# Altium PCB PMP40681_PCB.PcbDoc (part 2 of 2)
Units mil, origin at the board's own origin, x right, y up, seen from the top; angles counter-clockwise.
Board outline 1574.8 x 1574.8 mil, 4 copper layers (Top Layer, Signal Layer 1, Signal Layer 2, Bottom Layer), stack 67.2 mil thick; 42 components, 23 nets, 157 pads, 377 vias.
Unrouted connection lines stored in the file: 17.
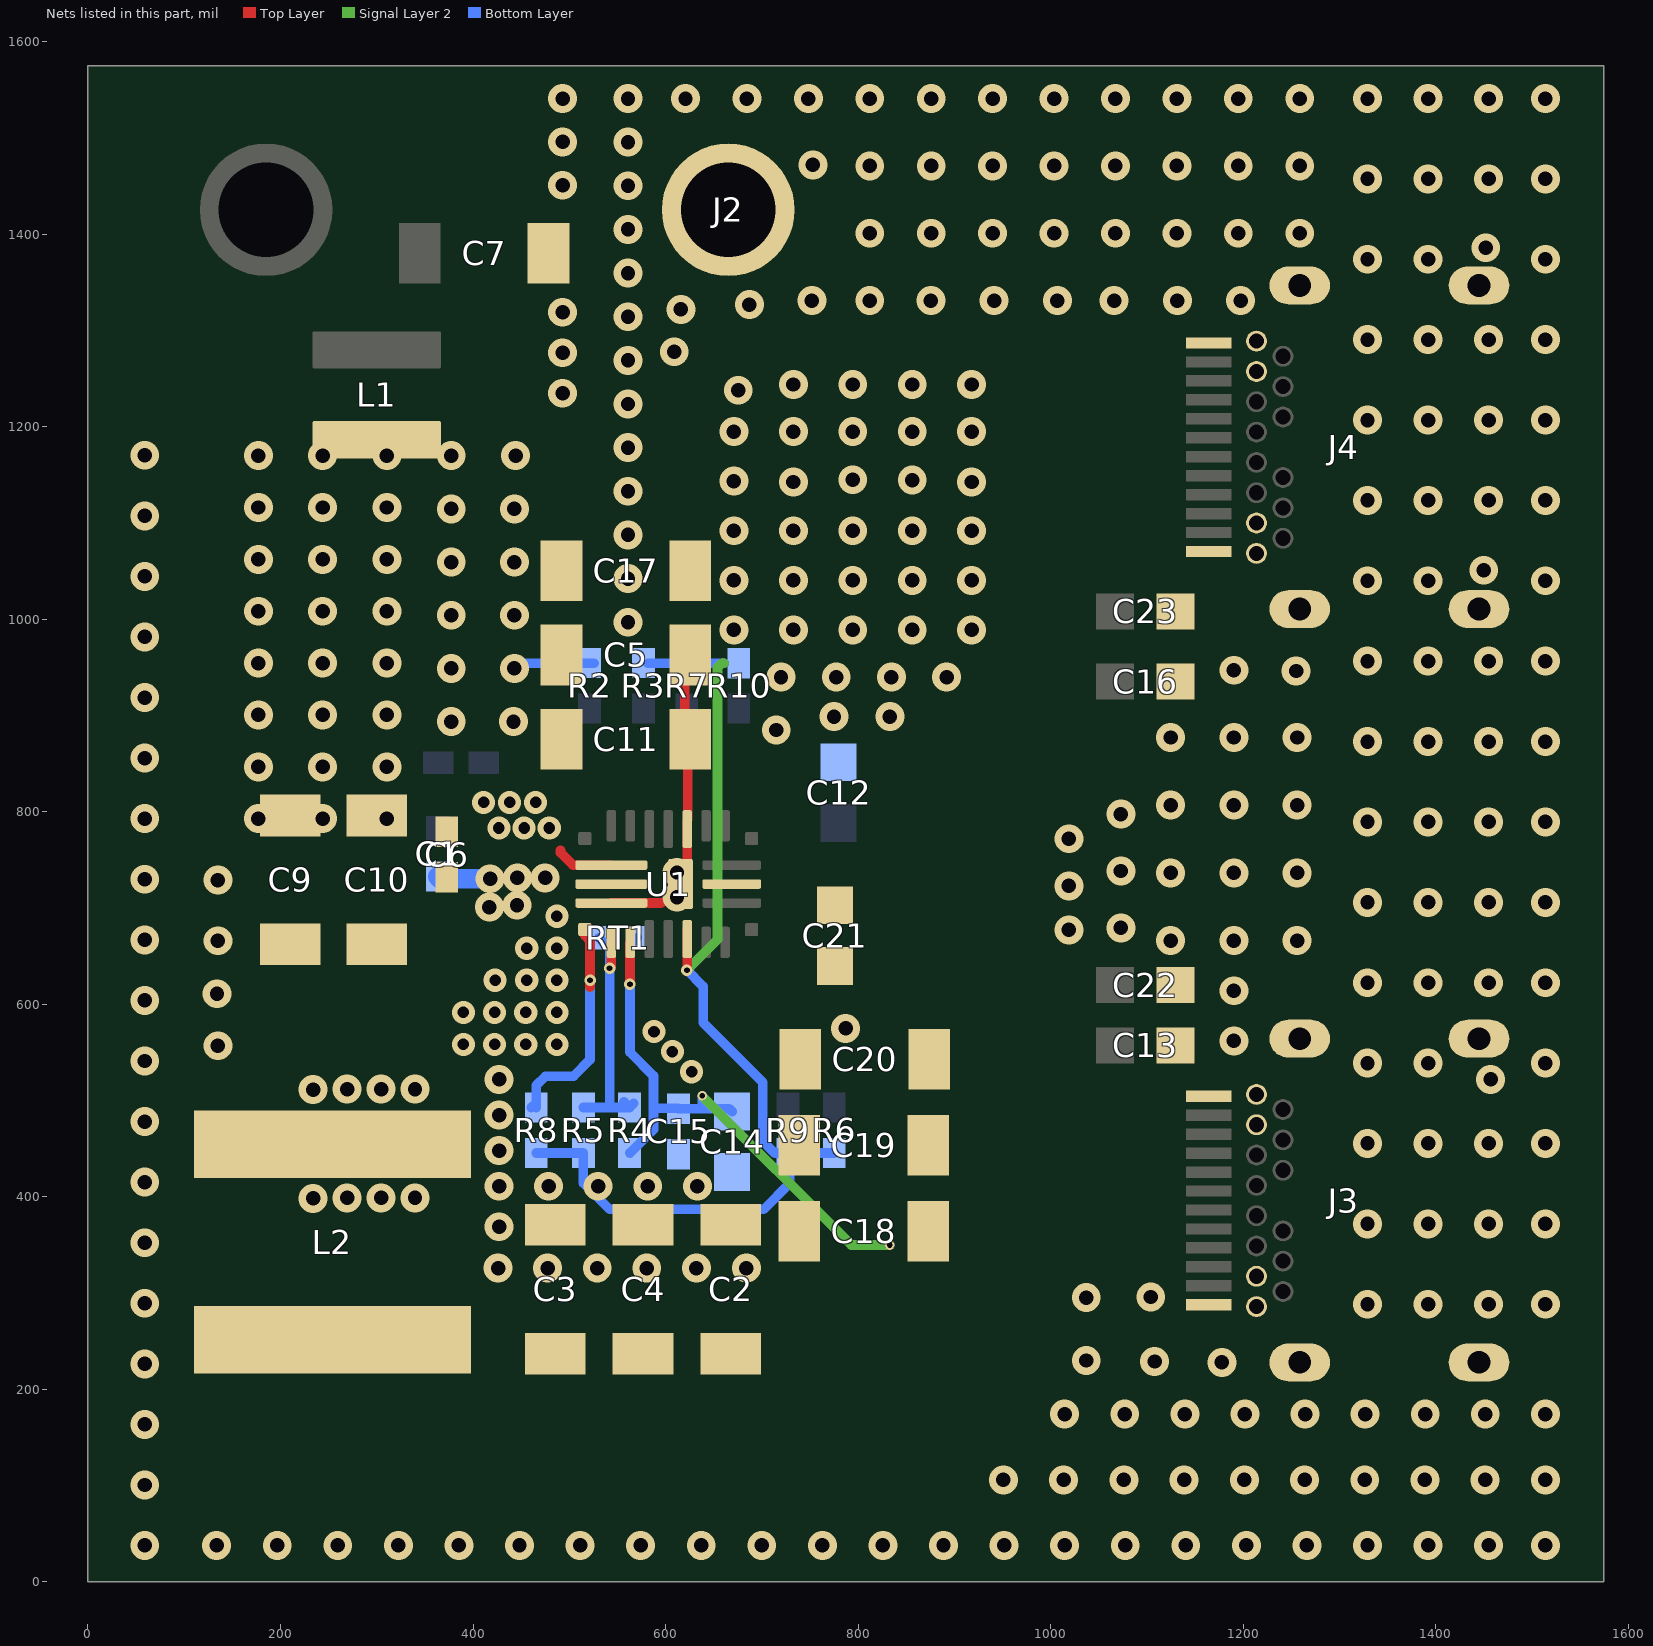
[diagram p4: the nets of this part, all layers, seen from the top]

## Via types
v1: diameter 30, hole 15, Top Layer to Bottom Layer, 321 vias
v2: diameter 24, hole 12, Top Layer to Bottom Layer, 28 vias
v3: diameter 12, hole 6, Top Layer to Bottom Layer, tented both sides, 14 vias
v4: diameter 12, hole 6, Top Layer to Bottom Layer, tented bottom, 6 vias
v5: diameter 10, hole 6, Top Layer to Bottom Layer, tented both sides, 5 vias
v6: diameter 24, hole 12, Top Layer to Bottom Layer, tented both sides, 3 vias

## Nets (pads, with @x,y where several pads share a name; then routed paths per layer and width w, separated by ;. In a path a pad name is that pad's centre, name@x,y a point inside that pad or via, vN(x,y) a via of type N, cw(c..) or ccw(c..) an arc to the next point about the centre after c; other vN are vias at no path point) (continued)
PGND: C2.2 C3.2 C4.2 C5.2 C6.2 C7.2 C9.2 C10.2 C11.2 C12.2 C13.2 C14.2 C15.2 C16.2 C17.2 C18.2 C19.2 C20.2 C21.2 C22.2 C23.2 J2.1 J3.A1 J3.A12 J3.B1 J3.B12 J3.M1 J3.M2 J3.S1 J3.S2 J3.S3 J3.S4 J4.A1 J4.A12 J4.B1 J4.B12 J4.M1 J4.M2 J4.S1 J4.S2 J4.S3 J4.S4 R3.1 R5.1 R6.2 R7.1 R8.2 R9.1 R10.1 U1.6 U1.16 U1.24 U1.25 | length 1417.7
  Top Layer w10: U1.24@543.71,705.27 595.34,705.27 595.56,705.48 ; C5.2@610.51,962.43 619.85,953.09 619.85,894.63 612.08,886.86 C11.2@622.18,877.76 ; U1.25@615.56,724.95 622.45,731.84 U1.16@622.45,782.04 622.45,791.45 623,792 623,876.84 622.13,877.71 C11.2@622.18,877.76 ; C11.2@621.18,878.96 C11.2@622.18,877.76 ; v3@622.45,639.92 U1.6@622.45,667.86 U1.6@622.45,678.64
  Signal Layer 2 w10: v3(622.13,635.48) 654,667.35 654,950 658.5,954.5 661,954.5
  Bottom Layer w10: R8.2@465.64,445.62 R5.1@514.64,445.62 514.64,414.36 542,387 702,387 728.85,413.85 R9.1@728.85,441.49 ; R3.1@581.5,954.5 629.85,954.5 661,954.5 ; v3(622.13,635.48) 639,618.61 639,581 700.81,519.19 700.81,458.19 713.38,445.62 750,445.62 ; R9.1@727.15,445.62 750,445.62 ; R6.2@775.2,445.62 750,445.62
  other v1: 59,38 133.63,38 196.56,38 259.48,38 322.41,38 385.33,38 448.26,38 511.19,38 574.11,38 637.04,38 699.96,38 762.89,38 825.82,38 888.74,38 951.67,38 1014.59,38 1077.52,38 1140.44,38 1203.37,38 1266.3,38 1329.22,38 1392.15,38 1455.07,38 1514,38 59,100.71 951,106 1013.56,106 1076.11,106 1138.67,106 1201.22,106 1263.78,106 1326.33,106 1388.89,106 1451.44,106 1514,106 59,163.63 1014.59,174.33 1077.02,174.33 1139.44,174.33 1201.87,174.33 1264.3,174.33 1326.72,174.33 1389.15,174.33 1451.57,174.33 1514,174.33 59,226.56 1178,228 1108,229 1037,230 1329.22,288.5 1392.15,288.5 1455.07,288.5 1514,288.5 59,289.48 1037,295.33 1104,296 426,326 477.5,326 529,326 580.5,326 632,326 684,326 59,352.41 427,369 1329.22,372 1392.15,372 1455.07,372 1514,372 427,411 478.5,411 530,411 581.5,411 633,411 59,415.33 427,448 1329.22,455.5 1392.15,455.5 1455.07,455.5 1514,455.5 59,478.26 427,485 427,522 1457,522 1329.22,539 1392.15,539 1514,539 59,541.19 135,557 1190.33,562 787,575 59,604.11 134,611 1190.33,614.12 1329.22,622.5 1392.15,622.5 1455.07,622.5 1514,622.5 135,666.07 1124.67,666.24 1190.33,666.24 1256,666.24 59,667.04 1019,677.37 1073,679.43 1329.22,706 1392.15,706 1455.07,706 1514,706 611.85,711.48 1019,723.02 135,729 59,729.96 611.85,736.97 1124.67,736.58 1190.33,736.58 1256,736.58 1073,738.52 1019,772 1329.22,789.5 1392.15,789.5 1455.07,789.5 1514,789.5 59,792.89 1073,797.61 1124.67,806.91 1190.33,806.91 1256,806.91 59,855.82 1329.22,873 1392.15,873 1455.07,873 1514,873 1124.67,877.24 1190.33,877.24 1256,877.24 715,885 775,899 833,899 59,918.74 719.92,940 777.28,940 834.64,940 892,940 1255,946.28 1190.33,947.11 1329.22,956.5 1392.15,956.5 1455.07,956.5 1514,956.5 59,981.67 671,989 732.75,989 794.5,989 856.25,989 918,989 561,997 671,1040.5 732.75,1040.5 794.5,1040.5 856.25,1040.5 918,1040.5 1329.22,1040 1392.15,1040 1514,1040 561,1042.33 59,1044.59 1450,1051 561,1087.67 671,1092 732.75,1092 794.5,1092 856.25,1092 918,1092 59,1107.52 1329.22,1123.5 1392.15,1123.5 1455.07,1123.5 1514,1123.5 561,1133 671,1143.5 732.75,1142.67 918,1142.67 794.5,1145 856.25,1144.6 59,1170.44 561,1178.33 671,1195 732.75,1195 794.5,1195 856.25,1195 918,1195 1329.22,1207 1392.15,1207 1455.07,1207 1514,1207 561,1223.67 493.11,1234.9 675.46,1237.91 732.75,1243.91 794.5,1243.91 856.25,1243.91 918,1243.91 561,1269 493.11,1276.95 609,1278 1329.22,1290.5 1392.15,1290.5 1455.07,1290.5 1514,1290.5 561,1314.33 493.11,1319 616,1322 687,1327 752,1331 812.14,1331 875.67,1331 941.33,1331 1007,1331 1066,1331 1131.67,1331 1197.33,1331 561,1359.67 1329.22,1374 1392.15,1374 1514,1374 1452,1386 812.14,1401 875.94,1401 939.75,1401 1003.55,1401 1067.36,1401 1131.16,1401 1194.97,1401 1258.78,1401 561,1405 561,1450.33 493.11,1450.95 1329.22,1457.5 1392.15,1457.5 1455.07,1457.5 1514,1457.5 812.14,1471 875.94,1471 939.75,1471 1003.55,1471 1067.36,1471 1131.16,1471 1194.97,1471 1258.78,1471 753,1472 493.11,1495.97 561,1495.67 493.11,1541 561,1541 620.72,1541 684.52,1541 748.33,1541 812.14,1541 875.94,1541 939.75,1541 1003.55,1541 1067.36,1541 1131.16,1541 1194.97,1541 1258.78,1541 1329.22,1541 1392.15,1541 1455.07,1541 1514,1541
  other v2: 390,558.46 422.39,558.46 454.79,558.46 487.18,558.46 390,591.73 422.39,591.73 454.79,591.73 487.18,591.73 423,625 455.78,625 487.18,625 455.78,658.28 487.18,658.28 487.18,691.55
  other v6: 627,530 607,551 588,571.64
SENS: C2.1 C3.1 C4.1 C14.1 C15.1 C18.1 C19.1 C20.1 C21.1 L2.2 R4.2 RT1.2 U1.3 U1.11 | length 647.6
  Top Layer w10: v3(563,621) 563,664.03 U1.3@563.39,664.42
  Signal Layer 2 w10: v5(638,505) 793,350 v5(832.79,350)
  Bottom Layer w10: R4.2@562.64,445.62 563.07,445.62 587.45,470 587.45,492 ; RT1.2@570.56,669.24 563,661.68 v3(563,621) 563,550.25 587.45,525.81 587.45,492 ; v5(638,505) 638,494.62 637,493.62 639,491.62 ; C14.1@669.11,488.76 666.24,491.62 639,491.62 ; 587.45,492 613.03,492 C15.1@613.41,491.62 639,491.62
SW: C1.1 L2.1 U1.23 | length 59
  Bottom Layer w10: v1@415.5,732.76 v1(417.79,730.46)
  Bottom Layer w20: C1.1@363,732.76 365.29,730.46 v1(417.79,730.46)
  other v1: 233.84,398.35 269.13,398.98 304.42,398.98 339.71,398.98 233.84,511.39 269.13,512.02 304.42,512.02 339.71,512.02 417,701 445.64,703 446,731.38 474.85,731.38
TS: R4.1 R5.2 RT1.1 U1.2 | length 271.7
  Top Layer w10: v3(541.85,637.48) 543.71,639.34 U1.2@543.71,664.42
  Bottom Layer w10: R5.2@514.64,492.86 540,492.86 ; RT1.1@530.56,669.24 541.85,657.95 v3(541.85,637.48) 541.85,494.71 540,492.86 ; R4.1@556.85,498.65 R4.1@562.64,492.86 ; R4.1@566.85,497.08 R4.1@562.64,492.86 ; 540,492.86 R4.1@562.64,492.86
VIN: C5.1 C6.1 C9.1 C10.1 C11.1 C17.1 L1.2 R2.2 U1.22 | length 145.8
  Top Layer w10: 490.85,759.98 490.85,757.62 503.84,744.64 U1.22@543.71,744.64
  Bottom Layer w10: v1(443,948.98) 448.52,954.5 R2.2@525.96,954.5
  other v1: 177,792.89 243.79,792.89 310.58,792.89 177,846.76 243.79,846.76 310.58,846.76 377.36,893.72 442,893.72 177,900.64 243.79,900.64 310.58,900.64 377.36,948.98 177,954.51 243.79,954.51 310.58,954.51 377.36,1004.23 443,1004.23 177,1008.38 243.79,1008.38 310.58,1008.38 377.36,1059.49 443,1059.49 177,1062.25 243.79,1062.25 310.58,1062.25 377.36,1114.74 443,1114.74 177,1116.13 243.79,1116.13 310.58,1116.13 177,1170 243.79,1170 310.58,1170 377.36,1170 444.15,1170
  other v2: 426.85,783.19 452.99,783.19 479.14,783.19 411,809.75 438,809.75 465,809.75
VSET: R8.1 U1.1 | length 238.1
  Top Layer w10: U1.1@516.15,677.71 516.15,671.41 521.56,666 v3(521.56,625) 521.56,617.79
  Bottom Layer w10: R8.1@460.64,492.86 R8.1@463.14,495.36 ; R8.1@465.64,492.86 465.64,515.79 475.17,525.32 504.39,525.32 521.56,542.49 v3(521.56,625)
pads on no net: J3.A2 J3.A3 J3.A8 J3.A10 J3.A11 J3.B2 J3.B3 J3.B8 J3.B10 J3.B11 J4.A2 J4.A3 J4.A8 J4.A10 J4.A11 J4.B2 J4.B3 J4.B8 J4.B10 J4.B11
copper on no net: | length 10
  Top Layer w10: 1154.61,426.53 1155.39,425.75 1164.25,425.75

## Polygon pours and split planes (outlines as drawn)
PGND on Top Layer "TOP_LAYER_PGND_P106" (solid, remove dead copper, pour order 106): 1,1578.91 1575.8,1578.91 1575.8,4.11 1,4.11
SW on Top Layer "TOP_LAYER_SW_P104" (solid, remove dead copper, pour order 104): 380,380 401,401 401,504 375.03,529.97 127.97,529.97 107,509 107,402 129,380
INPUT on Top Layer "TOP_LAYER_INPUT_P097" (solid, remove dead copper, pour order 97): 400,1285 369.46,1254.46 26.54,1254.46 0,1281 0,1574.8 400,1574.8
PA_BUS on Top Layer "TOP_LAYER_PA_BUS_P064" (solid, remove dead copper, pour order 64): 998.76,353.24 999.25,637.25 1008,646 1087,646 1096,637 1096,504.02 1111.69,488.33 1148.74,451.28 1162.84,451.33 1162.84,441.49 1162.84,363.3 1162.84,331.59 1020.92,331.08
SW on Top Layer "TOP_LAYER_SW_P008" (solid, remove dead copper, pour order 8): 437.04,672.54 412.87,672.54 400.79,684.62 400.79,738.32 411.56,749.08 479.9,749.08 496.74,732.24 592.85,732.24 592.85,719.05 483.54,719.04
PB_BUS on Top Layer "TOP_LAYER_PB_BUS_P024" (solid, remove dead copper, pour order 24): 638.75,752 689.85,752 721.92,784.06 722.1,825.74 769.73,873.46 858.06,873.46 963,978.4 963,1198 1018.85,1253.85 1114.82,1253.85 1132.1,1236.56 1221.16,1236.56 1227.05,1230.67 1227.05,1115.75 1141.92,1115.75 1092,1065.83 1092,892.49 953.8,754.28 719.92,754.29 705.64,740.01 639.24,740.01 638.33,740.93 638.75,741.36
VIN on Top Layer "TOP_LAYER_VIN_P010" (solid, remove dead copper, pour order 10): 120.8,1179.21 153.86,1213.19 473.55,1213.19 520.32,1166.43 520.32,808.61 508.05,796.34 508.07,749.56 564.38,749.56 564.38,739.71 508.08,739.71 500.14,739.71 482.55,757.3 163.53,757.3 120.8,800.02
SENS on Top Layer "TOP_LAYER_SENS_P004" (solid, remove dead copper, pour order 4): 739.09,701.84 759.94,681 800.54,681 812,669.54 812,344.8 767.2,300 120,300 98,278 98,154.87 132.87,120 915,120 990,195 990,714.24 958.24,746 722.82,746 706.7,729.87 638.48,729.87 638.48,720.88 639.18,720.18 705,720.18 723.34,701.84
PA_BUS on Top Layer "TOP_LAYER_PA_BUS_P022" (solid, remove dead copper, pour order 22): 738.21,596.93 745.85,604.57 745.85,687.48 740.19,693.14 720.19,693.14 703.14,710.19 638.18,710.19 638.18,700.34 698.19,700.34 706.82,691.71 706.82,605.26 715.15,596.93
PGND on Bottom Layer "BOTTOM_LAYER_PGND_P089" (solid, remove dead copper, pour order 89): 0,1574.8 1574.8,1574.8 1574.8,0 0,0
SW on Bottom Layer "BOTTOM_LAYER_SW_P117" (solid, remove dead copper, pour order 117): 178,723.41 203.74,749.15 480.14,748.95 489.85,739.45 489.85,725.35 432.75,668.26 360,595.5 360,523.87 360,386.11 353.38,379.49 191.62,379.49 178,393.11
VIN on Bottom Layer "BOTTOM_LAYER_VIN_P110" (solid, remove dead copper, pour order 110): 383.5,816.09 397.91,830.5 428,830.5 474.5,830.5 497.11,807.89 497.11,770.08 484.13,757.1 479.86,757.1 383.5,757.23
PA_BUS on Signal Layer 2 "SIGNAL_LAYER_2_PA_BUS_P060" (solid, remove dead copper, pour order 60): 806.44,698 965,698 1087,576 1087,510 1063,486 986.71,486 980,492.71 880.98,598 714.63,598 704.51,608.12 704.51,688.92 713.59,698
PGND on Signal Layer 2 "SIGNAL_LAYER_2_PGND_P108" (solid, remove dead copper, pour order 108): 1,1571.8 1575.8,1571.8 1575.8,-3 1,-3
VIN on Signal Layer 2 "SIGNAL_LAYER_2_VIN_P091" (solid, remove dead copper, pour order 91): 499.84,740.01 482.75,757.1 480.14,757.1 163.72,757.1 120,800.82 120,1178.87 152.13,1211 462,1211 480.14,1192.86 480.14,855.71 568.61,767.24 568.49,748.75 559.76,740.01
SW on Signal Layer 2 "SIGNAL_LAYER_2_SW_P034" (solid, remove dead copper, pour order 34): 178,723.41 203.74,749.15 480.14,748.95 489.85,739.45 489.85,725.35 432.75,668.26 360,595.5 360,523.87 360,386.11 353.38,379.49 191.62,379.49 178,393.11
PGND on Signal Layer 1 "SIGNAL_LAYER_1_PGND_P107" (solid, remove dead copper, pour order 107): 0,1574.8 1574.8,1574.8 1574.8,0 0,0

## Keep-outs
Keep-Out Layer:
  text ".Layer_Name" at 577,-858.49 h60

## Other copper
Top Layer:
  pour cut-out: 99.46,398.88 102.1,396.24 102.1,293.64 102.98,293.64 116.88,307.54 408.46,307.54 410,309.08 404.08,315 404,315 404,391 387.23,374.23 123.23,374.23 101.23,396.23
  pour cut-out: 405,1564.61 448.59,1564.61 448.59,1245.99 405,1245.99
  pour cut-out: 447,1215 447,1254.46 5,1254.46 5,1215
  pour cut-out: 630,767.56 630,707.68 634.68,707.68 634.96,773.19
  pour cut-out: 586.55,714.81 590.08,718.34 590.08,747.65 586.26,751.48 584.85,751.48 584.31,751.73 583.03,750.45 583.03,714.81
  pour cut-out: 536.92,698.48 605.11,698.48 605.11,689.08 550.25,688.72 548.65,690.32 536.53,690.32
  text ".Layer_Name" at 577,-858.49 h60
Bottom Layer:
  pour cut-out: 522.8,688.99 523.05,689.24 587.07,689.24 587.07,684.28 587.03,684.24 522.8,684.24
  pour cut-out: 1258.31,428.23 1258.56,427.98 1258.56,363.96 1253.6,363.96 1253.56,364 1253.56,428.23
  pour cut-out: 1254.25,1145.77 1254,1146.02 1254,1210.04 1258.96,1210.04 1259,1210 1259,1145.77
  pour cut-out: 719.77,474.96 720.02,475.21 784.04,475.21 784.04,470.25 784,470.21 719.77,470.21
  pour cut-out: 459.22,471.87 546.06,472.21 546.06,469.03 459.22,468.98
  pour cut-out: 594.49,465.41 594.74,465.66 658.76,465.66 658.76,460.7 658.72,460.66 594.49,460.66
  pour cut-out: 545.77,930.75 546.02,931 610.04,931 610.04,926.04 610,926 545.77,926
  text ".Layer_Name" at 577,-858.49 h60

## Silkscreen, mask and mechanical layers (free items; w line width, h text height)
Top Overlay:
  text "VIN" at 341,1446 h72.83 r90
  text "GND" at 866.06,1411.15 h72.83 r90
  text "PMP40681E1" at 419,56 h50
  text ".Layer_Name" at 577,-858.49 h60
Bottom Overlay:
  text ".Layer_Name" at 577,-858.49 h60
Top Paste:
  text ".Layer_Name" at 577,-858.49 h60
Bottom Paste:
  text ".Layer_Name" at 577,-858.49 h60
Top Solder:
  region: 381.39,464.09 331.39,464.09 331.39,432.21 381.39,432.21
  region: 397,779 397,818 409.5,830.5 476.5,830.5 500.31,806.69 500.31,783.08 500.31,755.01 503.72,751.6 523.04,751.61 523.04,737.62 502.23,737.62 473.85,766 410,766
  region: 494,580 500.97,586.97 500.97,635.4 500.97,690.8 509.07,698.9 509.07,712.48 487.18,712.48 436,661.3 436,589 445,580
  region: 692.85,738.06 702.45,738.06 731.36,766.97 723.38,774.95 692.85,744.43
  region: 695.65,712.48 695.65,702.88 713.38,685.16 721.36,693.14 702.02,712.48
  region: 517.57,718.48 484.37,718.48 484.37,731.48 504.57,731.48 517.57,731.48
  region: 696.65,731.48 729.85,731.48 729.85,718.48 709.65,718.48 696.65,718.48
  text ".Layer_Name" at 577,-858.49 h60
  text ".Layer_Name" at 577,-858.49 h60
Bottom Solder:
  rectangle: 588,690 635,759
  text ".Layer_Name" at 577,-858.49 h60
Drill Guide:
  text ".Layer_Name" at 577,-858.49 h60
M1 Board Outline:
  lines w0.39: 0,1968.5 0,1968.5
  lines w1: 0,0 0,1574.8 1574.8,1574.8 1574.8,0 0,0
  text ".Layer_Name" at 577,-858.49 h60
M2 Board Dimensions:
  rectangle: 0,-275 125,-150
  rectangle: 125,-400 500,-275
  lines w7: 0,-275 1000,-275 ; 125,-400 125,-150 ; 250,-400 250,-150 ; 500,-400 500,-150 ; 750,-400 750,-150 ; 0,-400 1000,-400 1000,-150 0,-150 0,-400
  text ".Layer_Name" at 577,-858.49 h60
M3 3D STEP Top:
  text ".Layer_Name" at 577,-858.49 h60
M4 3D STEP Bottom:
  text ".Layer_Name" at 577,-858.49 h60
M5 Assembly Top:
  lines w10: -292,-930.17 6308,-930.17 ; -292,-726.83 6310,-726.83 ; -292,-523.5 -292,-1133.5 3713,-1133.5 6310,-1133.5 6310,-523.5 -291.5,-523.5 -291.5,-1133.5 1284,-1133.5 ; 2173,-1133.5 2173,-523.5 ; 3440,-726.83 3440,-523.5 ; 4280,-726.83 4280,-523.5 ; 4902,-1140 4902,-937.17
  text "COMPONENTS MARKED 'DNP' SHOULD NOT BE POPULATED." at 1153.5,-318.5 h60
  text "ASSEMBLY VARIANT:" at 1153,-434 h60
  text ".VariantName" at 2189,-434 h60
  text "PCB VIEWED FROM TOP SIDE" at -228.5,-655.67 h60
  text "BOARD #:" at 2248,-655.67 h60
  text ".PRJ_Number" at 2793.5,-655.67 h60
  text "REV:" at 3638,-655.67 h60
  text ".PCB_Rev" at 3929.5,-655.67 h60
  text "SVN REV:" at 4476,-655.67 h60
  text ".VersionControl_RevNumber" at 4982,-655.67 h60
  text "TID #:" at 2248,-859 h60
  text ".TID" at 2793.5,-859 h60
  text "PLOT NAME =" at -228.5,-1064.34 h60
  text ".plot_File_Name" at 577,-1064.34 h60
  text "GENERATED    :" at 2250,-1064.34 h60
  text ".Print_Date" at 3119.5,-1064.34 h60
  text ".Print_Time" at 3848.5,-1064.34 h60
  text "TEXAS INSTRUMENTS" at 5113,-1064.34 h60
M6 Assembly Bottom:
  lines w10: -292.5,-727.33 6309.5,-727.33 ; -290.5,-930.67 6309.5,-930.67 ; 1115.5,-1140.5 1115.5,-937.67 ; 1737.5,-727.33 1737.5,-524 ; 2577.5,-727.33 2577.5,-524 ; 3844.5,-1134 3844.5,-524 ; 4733.5,-1134 6309,-1134 6309,-524 -292.5,-524 -292.5,-1134 2304.5,-1134 6309.5,-1134 6309.5,-524
  text "COMPONENTS MARKED 'DNP' SHOULD NOT BE POPULATED." at 6102,-318 h60
  text ".VariantName" at 5058,-434 h60
  text "ASSEMBLY VARIANT:" at 6097,-434 h60
  text ".VersionControl_RevNumber" at 1035.5,-656.17 h60
  text "SVN REV:" at 1541.5,-656.17 h60
  text ".PCB_Rev" at 2088,-656.17 h60
  text "REV:" at 2379.5,-656.17 h60
  text ".PRJ_Number" at 3224,-656.17 h60
  text "BOARD #:" at 3769.5,-656.17 h60
  text "PCB VIEWED FROM BOTTOM SIDE" at 6246,-656.17 h60
  text ".TID" at 3224,-859.5 h60
  text "TID #:" at 3769.5,-859.5 h60
  text "TEXAS INSTRUMENTS" at 904.5,-1064.84 h60
  text ".Print_Time" at 2169,-1064.84 h60
  text ".Print_Date" at 2898,-1064.84 h60
  text "GENERATED    :" at 3767.5,-1064.84 h60
  text ".plot_File_Name" at 5440.5,-1064.84 h60
  text "PLOT NAME =" at 6246,-1064.84 h60
M9 Title Sheet:
  drawing of 57 lines, arcs and shapes, not listed
  text "1" at 739.84,8036.5 h70
  text "2" at 3235.5,8036.5 h70
  text "3" at 5724.84,8036.5 h70
  text "4" at 8231.51,8036.5 h70
  text "5" at 10730.5,8036.5 h70
  text "6" at 13235.5,8036.5 h70
  text "A" at -416.5,6893.5 h70
  text "A" at 14383.5,6893.5 h70
  text "B" at -416.5,4513.5 h70
  text "B" at 14383.5,4513.5 h70
  text "C" at -416.5,2138.5 h70
  text "C" at 14383.5,2138.5 h70
  text "PROJECT TITLE:" at 11343.5,277.5 h45
  text ".PRJ_Title" at 11393.5,144.17 h70
  text "DESIGNED FOR:" at 11343.5,-23.5 h45
  text ".PRJ_Customer" at 11393.5,-163.5 h70
  text "D" at -416.5,-231.5 h70
  text "D" at 14383.5,-231.5 h70
  text "FILE NAME:" at 11343.5,-323.5 h45
  text ".PCB_File_Name_No_Path" at 11393.5,-443.5 h70
  text "Texas Instruments (TI) and/or its licensors do not warrant the accuracy or completeness of this specification" at 6374,-605.34 h45
  text "ENGINEER:" at 11343.5,-613.5 h45
  text "LAYOUT BY:" at 12848.5,-613.5 h45
  text "or any information contained therein. TI and/or its licensors do not warrant that this design will meet" at 6329.01,-718 h45
  text ".PRJ_Engineer" at 11393.5,-768.49 h70
  text ".PCB_Layout" at 12899,-768.49 h70
  text "the specifications, will be suitable for your application or fit for any particular purpose, or will operate in" at 6329.01,-830.67 h45
  text ".Layer_Name" at 577,-858.49 h60
  text "ALTIUM DESIGNER VERSION:" at 12848.5,-923.5 h45
  text "an implementation. TI and/or its licensors do not warrant that the design is production worthy. You should" at 6329.01,-943.33 h45
  text "completely validate and test your design implementation to confirm the system functionality for your application." at 6374,-1056 h45
  text ".print_Scale" at 11393.5,-1056.83 h70
  text ".Application_BuildNumber" at 12899,-1056.83 h70
  text "1" at 739.84,-1263.5 h70
  text "2" at 3235.5,-1263.5 h70
  text "3" at 5724.84,-1263.5 h70
  text "4" at 8231.51,-1263.5 h70
  text "5" at 10730.5,-1263.5 h70
  text "6" at 13235.5,-1263.5 h70
M10 Fab Notes:
  drawing of 189 lines, arcs and shapes, not listed
  text "DESIGN INFORMATION" at 12382.02,6356.17 h60
  text "MIN. TRACK WIDTH:" at 11737.46,6224.05 h60
  text "8" at 12833.7,6224.05 h60
  text "MIL" at 12988.46,6224.05 h60
  text "MIN. CLEARANCE:" at 11737.46,6099.92 h60
  text "0.2" at 12773.7,6099.93 h60
  text "mm" at 12988.46,6099.92 h60
  text "MIN. VIA PAD SIZE:" at 11737.46,5975.8 h60
  text "24" at 12803.71,5975.8 h60
  text "MIL" at 12988.46,5975.8 h60
  text "0.05mm (2MIL)" at 12432.46,5845.9 h60
  text "MINIMUM ANNULAR RING" at 11408.23,5837.67 h60
  text "EXTERNAL" at 13140.46,5837.67 h60
  text "PER" at 11608.23,5727.55 h60
  text "IPC-D-275 CLASS 2 LEVEL C" at 11828.23,5727.54 h60
  text "MIL, HOLES" at 13316.46,5627.07 h60
  text "+/-" at 12924,5618.48 h60
  text "+/-" at 13778,5618.48 h60
  text "REGISTRATION TOLERANCES:" at 11408.23,5617.42 h60
  text "METAL" at 12608,5617.42 h60
  text "5" at 13184.2,5617.42 h60
  text "3" at 14017.2,5617.42 h60
  text "MIL" at 14133.46,5617.42 h60
  text "HOLE SIZE TOLERANCE (UNLESS OTHERWISE SPECIFIED):" at 11408.23,5519.1 h60
  text "+/-" at 13778,5516.23 h60
  text "3" at 14017.2,5515.17 h60
  text "MIL" at 14133.46,5515.17 h60
  text "MATERIAL:" at 11333.46,5377.52 h60
  text "FR-4 High Tg" at 12319.9,5249 h60
  text "X" at 12175.46,5241.01 h60
  text "FR-408" at 11754.46,5236.49 h60
  text "OTHER" at 13242.46,5236.49 h60
  text "62 MIL (1.6mm) +/-10%" at 12074.56,5093.46 h60
  text "X" at 11954.46,5091.01 h60
  text "THICKNESS:" at 11408.23,5085.24 h60
  text "OTHER" at 13359.46,5085.24 h60
  text "TOLERANCE:" at 11408.23,4946.92 h60
  text "X" at 12256.46,4946.92 h60
  text "ANSI IPC-6012 TYPE 3 CLASS 2" at 12434.48,4946.92 h60
  text "OTHER +/-" at 12434.46,4802.73 h60
  text "BOW & TWIST:" at 11408.23,4657.54 h60
  text "X" at 12256.46,4657.54 h60
  text "ANSI IPC-6012 TYPE 3 CLASS 2" at 12434.48,4657.54 h60
  text "OTHER +/-" at 12434.46,4510.85 h60
  text "DRILLING:" at 11333.46,4380.23 h60
  text "NC_DRILL FILES" at 13094.46,4275.04 h60
  text "REFERENCE:" at 11408.23,4271.1 h60
  text "X" at 12065.46,4271.01 h60
  text "AS SHOWN" at 12243.46,4271.1 h60
  text "X" at 12966.46,4271.1 h60
  text "OTHER" at 13392.46,4128.85 h60
  text "PTH COPPER THICKNESS:" at 11407.91,4125.32 h60
  text "X" at 12547.14,4125.32 h60
  text "20-30 um" at 12675.14,4125.32 h60
  text "BOARD FINISH:" at 11333.46,3977.73 h60
  text "SILKSCREEN:" at 11488.68,3867.6 h60
  text "X" at 12446.46,3867.6 h60
  text "TOP" at 12563.46,3867.6 h60
  text "X" at 12956.46,3867.6 h60
  text "BOTTOM" at 13074.46,3867.6 h60
  text "SILKSCREEN COLOR:" at 11488.68,3712.41 h60
  text "X" at 12445.46,3712.41 h60
  text "WHITE" at 12563.46,3712.41 h60
  text "OTHER" at 13074.46,3712.41 h60
  text "X" at 12576.46,3568.96 h60
  text "GREEN" at 12694.46,3568.96 h60
  text "OTHER" at 13312.46,3568.96 h60
  text "SOLDER RESIST COLOR:" at 11488.68,3562.1 h60
  text "X" at 12576.46,3414.71 h60
  text "MATTE" at 12694.46,3414.71 h60
  text "SEMI-GLOSS" at 13312,3414.07 h60
  text "IMMERSION GOLD (ENIG)" at 12394.46,3241.94 h60
  text "ENEPIG" at 13732,3234.72 h60
  text "SURFACE FINISH:" at 11333.46,3233.72 h60
  text "X" at 12216.46,3233.72 h60
  text "IMM. TIN/SILVER OR EQUIV" at 11663,3096.4 h60
  text "OTHER" at 13094.46,3092.47 h60
  text "ARRAY/PANEL:" at 11333.46,2937.09 h60
  text "CUT AND TRIM PER M1 BOARD OUTLINE" at 12394.46,2928.87 h60
  text "N.C. ROUTE" at 12394.46,2792.9 h60
  text "V. SCORE" at 13260.46,2792.9 h60
  text "CERTIFICATION:" at 11333.46,2663.77 h60
  text "MATERIALS AND WORKMANSHIP FOR ALL PCBS" at 12058.46,2663.77 h60
  text "TO MEET OR EXCEED THE REQUIREMENTS OF:" at 12058.46,2569.71 h60
  text "X" at 11695.97,2441.08 h60
  text "ANSI IPC-A-600F CLASS ->" at 11823.96,2441.08 h60
  text "X" at 13471.97,2441.08 h60
  text "2" at 13581.96,2441.08 h60
  text "1" at 13266.96,2439.58 h60
  text "3" at 13935.96,2439.58 h60
  text "X" at 12507.97,2293.39 h60
  text "RoHS" at 12635.96,2293.39 h60
  text "OTHER" at 13280.36,2293.39 h60
  text "PER ORDER" at 13677.42,2293.39 h60
  text "ALL BOARDS MUST MEET OR EXCEED UL94-V0 REQUIREMENTS." at 11361,2139.57 h60
  text "PCB MUST BEAR THE UL94V-0 UL REGISTERED MATERIAL ID NUMBER" at 11361,2023.5 h60
  text "ADDITIONAL REQUIREMENTS:" at 11333.46,1854.08 h60
  text "MICROSECTION:" at 11408.23,1746.95 h60
  text "YES" at 12313.96,1746.95 h60
  text "REQUIRED" at 13175.46,1602.62 h60
  text "BARE BOARD ELEC. TEST:" at 11408.23,1599.76 h60
  text "NONE" at 12713.96,1599.76 h60
  text "X" at 13057.46,1599.76 h60
  text "PER ORDER" at 13767.46,1599.76 h60
  text "XX MIL VIAS REQUIRE NON-CONDUCTIVE FILL AND PLANARIZE" at 11576.38,1394.82 h59
  text "XX MIL VIAS REQUIRE CONDUCTIVE FILL AND PLANARIZE" at 11584.38,1290.84 h60
  text "OUTER XX MIL TRACES REQUIRE 50 OHM SINGLE-ENDED IMPEDANCE" at 11583.39,1127.46 h58
  text "LAYER 2 & 3 (INNER LAYERS) XX MIL WIDE, XX MIL SPACE / TRACES REQUIRE 100 OHM DIFFERENTIAL IMPEDANCE" at 11575.39,891.74 h60
  text ".Layer_Name" at 577,-858.49 h60
M11 Gerber Information:
  lines w10: -292,-930.17 6308,-930.17 ; -292,-726.83 6310,-726.83 ; -292,-523.5 -292,-1133.5 3713,-1133.5 6310,-1133.5 6310,-523.5 -291.5,-523.5 -291.5,-1133.5 1284,-1133.5 ; 2173,-1133.5 2173,-523.5 ; 3440,-726.83 3440,-523.5 ; 4280,-726.83 4280,-523.5 ; 4902,-1140 4902,-937.17
  text "ALL ARTWORK VIEWED FROM TOP SIDE" at -228.5,-655.67 h60
  text "BOARD #:" at 2248,-655.67 h60
  text ".PRJ_Number" at 2793.5,-655.67 h60
  text "REV:" at 3638,-655.67 h60
  text ".PCB_Rev" at 3929.5,-655.67 h60
  text "SVN REV:" at 4476,-655.67 h60
  text ".VersionControl_RevNumber" at 4982,-655.67 h60
  text "LAYER NAME =" at -228.5,-858.49 h60
  text "TID #:" at 2248,-859 h60
  text ".TID" at 2793.5,-859 h60
  text "PLOT NAME =" at -228.5,-1064.34 h60
  text ".plot_File_Name" at 577,-1064.34 h60
  text "GENERATED    :" at 2250,-1064.34 h60
  text ".Print_Date" at 3119.5,-1064.34 h60
  text ".Print_Time" at 3848.5,-1064.34 h60
  text "TEXAS INSTRUMENTS" at 5113,-1064.34 h60
M12 Stackup:
  drawing of 527 lines, arcs and shapes, not listed
  text "Layer" at 5012.09,5925.5 h60
  text "Name" at 5422,5925.5 h60
  text "Material" at 6361.74,5925.5 h60
  text "Thickness" at 7221.51,5925.5 h60
  text "Constant" at 7871.34,5925.5 h60
  text "Board Layer Stack" at 8441.2,5925.5 h60
  text "Board Layer Stack" at 9560.89,5925.5 h60
  text "1" at 5012.09,5805.5 h60
  text "Top Overlay" at 5422,5805.5 h60
  text "2" at 5012.09,5685.5 h60
  text "Top Solder" at 5422,5685.5 h60
  text "Solder Resist" at 6361.74,5685.5 h60
  text "0.40mil" at 7221.51,5685.5 h60
  text "3.5" at 7871.34,5685.5 h60
  text "3" at 5012.09,5565.5 h60
  text "Top Layer" at 5422,5565.5 h60
  text "Copper" at 6361.74,5565.5 h60
  text "2.80mil" at 7221.51,5565.5 h60
  text "4" at 5012.09,5445.5 h60
  text "Dielectric 1" at 5422,5445.5 h60
  text "FR-4" at 6361.74,5445.5 h60
  text "8.00mil" at 7221.51,5445.5 h60
  text "4.2" at 7871.34,5445.5 h60
  text "5" at 5012.09,5325.5 h60
  text "Signal Layer 1" at 5422,5325.5 h60
  text "Copper" at 6361.74,5325.5 h60
  text "2.80mil" at 7221.51,5325.5 h60
  text "6" at 5012.09,5205.5 h60
  text "Dielectric 2" at 5422,5205.5 h60
  text "FR-4" at 6361.74,5205.5 h60
  text "40.00mil" at 7221.51,5205.5 h60
  text "4.2" at 7871.34,5205.5 h60
  text "7" at 5012.09,5085.5 h60
  text "Signal Layer 2" at 5422,5085.5 h60
  text "Copper" at 6361.74,5085.5 h60
  text "2.80mil" at 7221.51,5085.5 h60
  text "8" at 5012.09,4965.5 h60
  text "Dielectric 3" at 5422,4965.5 h60
  text "FR-4" at 6361.74,4965.5 h60
  text "8.00mil" at 7221.51,4965.5 h60
  text "4.2" at 7871.34,4965.5 h60
  text "9" at 5012.09,4845.5 h60
  text "Bottom Layer" at 5422,4845.5 h60
  text "Copper" at 6361.74,4845.5 h60
  text "2.80mil" at 7221.51,4845.5 h60
  text "10" at 5012.09,4725.5 h60
  text "Bottom Solder" at 5422,4725.5 h60
  text "Solder Resist" at 6361.74,4725.5 h60
  text "0.40mil" at 7221.51,4725.5 h60
  text "3.5" at 7871.34,4725.5 h60
  text "11" at 5012.09,4605.5 h60
  text "Bottom Overlay" at 5422,4605.5 h60
  text ".Layer_Name" at 577,-858.49 h60
M13 Component Bodies Top:
  text ".Layer_Name" at 577,-858.49 h60
M14 Component Bodies Bottom:
  text ".Layer_Name" at 577,-858.49 h60
M15 Courtyards Top:
  text ".Layer_Name" at 577,-858.49 h60
M16 Courtyards Bottom:
  text ".Layer_Name" at 577,-858.49 h60
Drill Drawing:
  circle w10: c5363.72,4224.13 r27.63
  lines w10: 5336.09,3574.91 5391.34,3574.91 5391.34,3630.16 5336.09,3630.16 5336.09,3574.91 ; 5336.09,3699.23 5363.72,3713.04 5391.34,3699.23 5377.53,3726.85 5391.34,3754.48 5363.72,3740.67 5336.09,3754.48 5349.9,3726.85 5336.09,3699.23 ; 5336.09,3878.8 5391.34,3878.8 5363.72,3823.55 5336.09,3878.8 ; 5336.09,3975.49 5363.72,3947.87 5391.34,3975.49 5363.72,4003.12 5336.09,3975.49 ; 5336.09,4086 5349.9,4086 5363.72,4072.19 5377.53,4086 5391.34,4086 5377.53,4099.81 5391.34,4113.63 5377.53,4113.63 5363.72,4127.44 5349.9,4113.63 5336.09,4113.63 5349.9,4099.81 5336.09,4086
  lines w12: 5286,3537.61 8517.49,3537.61 ; 5286,4283.53 8517.49,4283.53 ; 5623.86,3413.29 5623.86,4407.85 ; 5955.86,3413.29 5955.86,4407.85 ; 6592.43,3413.29 6592.43,4407.85 ; 6851.57,3413.29 6851.57,4407.85 ; 7226.72,3413.29 7226.72,4407.85 ; 7951.05,3413.29 7951.05,4407.85 ; 5286,3413.29 8517.49,3413.29 8517.49,4407.85 5286,4407.85 5286,3413.29
  text "Symbol" at 5360.59,4320.83 h72
  text "Quantity" at 5661.16,4320.83 h72
  text "Finished Hole Size" at 5993.16,4320.83 h72
  text "Plated" at 6629.72,4320.83 h72
  text "Hole Type" at 6888.86,4320.83 h72
  text "Drill Layer Pair" at 7264.02,4320.83 h72
  text "Hole Tolerance" at 7988.35,4320.83 h72
  text "25" at 5661.16,4196.51 h60
  text "6.00mil (0.152mm)" at 5993.16,4196.51 h60
  text "PTH" at 6629.72,4196.51 h60
  text "Round" at 6888.86,4196.51 h60
  text "Top Layer - Bottom Layer" at 7264.02,4196.51 h60
  text "31" at 5661.16,4072.19 h60
  text "12.00mil (0.305mm)" at 5993.16,4072.19 h60
  text "PTH" at 6629.72,4072.19 h60
  text "Round" at 6888.86,4072.19 h60
  text "Top Layer - Bottom Layer" at 7264.02,4072.19 h60
  text "321" at 5661.16,3947.87 h60
  text "15.00mil (0.381mm)" at 5993.16,3947.87 h60
  text "PTH" at 6629.72,3947.87 h60
  text "Round" at 6888.86,3947.87 h60
  text "Top Layer - Bottom Layer" at 7264.02,3947.87 h60
  text "28" at 5661.16,3823.55 h60
  text "15.75mil (0.400mm)" at 5993.16,3823.55 h60
  text "PTH" at 6629.72,3823.55 h60
  text "Round" at 6888.86,3823.55 h60
  text "Top Layer - Bottom Layer" at 7264.02,3823.55 h60
  text "2" at 5661.16,3699.23 h60
  text "98.43mil (2.500mm)" at 5993.16,3699.23 h60
  text "PTH" at 6629.72,3699.23 h60
  text "Round" at 6888.86,3699.23 h60
  text "Top Layer - Bottom Layer" at 7264.02,3699.23 h60
  text "8" at 5661.16,3574.91 h60
  text "23.62mil (0.600mm)" at 5993.16,3574.91 h60
  text "PTH" at 6629.72,3574.91 h60
  text "Slot" at 6888.86,3574.91 h60
  text "Top Layer - Bottom Layer" at 7264.02,3574.91 h60
  text "415 Total" at 5661.16,3450.59 h60
  text "Slot definitions :" at 5360.59,3363.56 h60
  text "Routed Path Length" at 5811.31,3363.56 h60
  text "= Calculated from tool start centre position to tool end centre position." at 6351.05,3363.56 h60
  text "Hole Length" at 5811.31,3313.83 h60
  text "= Routed Path Length + Tool Size = Slot length as defined in the PCB layout" at 6151.24,3313.83 h60
  text ".Layer_Name" at 577,-858.49 h60
Mechanical 17:
  text ".Layer_Name" at 577,-858.49 h60
Mechanical 18:
  text ".Layer_Name" at 577,-858.49 h60
Mechanical 19:
  text ".Layer_Name" at 577,-858.49 h60

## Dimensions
0,0 to 1574.8,0 on M2 Board Dimensions
0,0 to 0,1574.8 on M2 Board Dimensions
0,-400 to 1000,-400 on M2 Board Dimensions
